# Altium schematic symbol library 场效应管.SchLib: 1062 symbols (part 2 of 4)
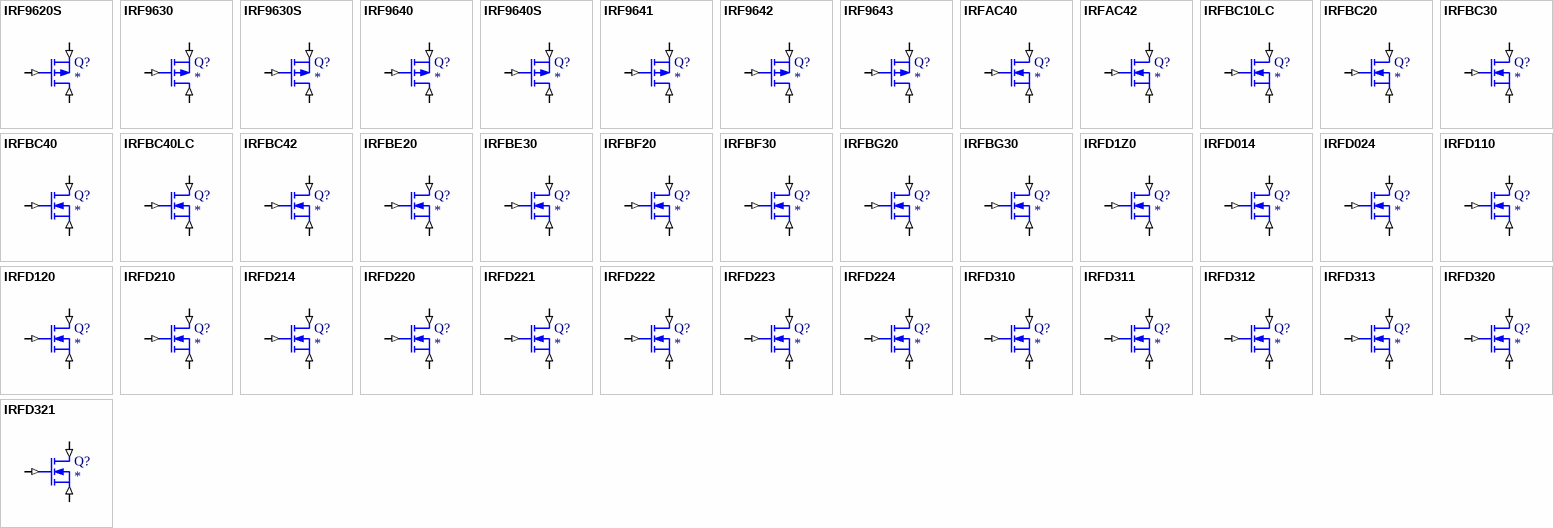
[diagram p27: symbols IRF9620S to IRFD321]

## IRFBC40
designator Q?
N-Channel MOSFET
simulation model IRFBC40 (SUBCKT)
pins: 1 D (in), 2 G (in), 3 S (in)
1 alternate drawing of the same symbol

## IRFBC40LC
designator Q?
N-Channel MOSFET
simulation model IRFBC40LC (SUBCKT)
pins: 1 D (in), 2 G (in), 3 S (in)
1 alternate drawing of the same symbol

## IRFBC42
designator Q?
N-Channel MOSFET
simulation model IRFBC42 (SUBCKT)
pins: 1 D (in), 2 G (in), 3 S (in)
1 alternate drawing of the same symbol

## IRFBE20
designator Q?
N-Channel MOSFET
simulation model IRFBE20 (SUBCKT)
pins: 1 D (in), 2 G (in), 3 S (in)
1 alternate drawing of the same symbol

## IRFBE30
designator Q?
N-Channel MOSFET
simulation model IRFBE30 (SUBCKT)
pins: 1 D (in), 2 G (in), 3 S (in)
1 alternate drawing of the same symbol

## IRFBF20
designator Q?
N-Channel MOSFET
simulation model IRFBF20 (SUBCKT)
pins: 1 D (in), 2 G (in), 3 S (in)
1 alternate drawing of the same symbol

## IRFBF30
designator Q?
N-Channel MOSFET
simulation model IRFBF30 (SUBCKT)
pins: 1 D (in), 2 G (in), 3 S (in)
1 alternate drawing of the same symbol

## IRFBG20
designator Q?
N-Channel MOSFET
simulation model IRFBG20 (SUBCKT)
pins: 1 D (in), 2 G (in), 3 S (in)
1 alternate drawing of the same symbol

## IRFBG30
designator Q?
N-Channel MOSFET
simulation model IRFBG30 (SUBCKT)
pins: 1 D (in), 2 G (in), 3 S (in)
1 alternate drawing of the same symbol

## IRFD1Z0
designator Q?
N-Channel MOSFET
simulation model IRFD1Z0 (SUBCKT)
pins: 1 D (in), 2 G (in), 3 S (in)
1 alternate drawing of the same symbol

## IRFD014
designator Q?
N-Channel MOSFET
simulation model IRFD014 (SUBCKT)
pins: 1 D (in), 2 G (in), 3 S (in)
1 alternate drawing of the same symbol

## IRFD024
designator Q?
N-Channel MOSFET
simulation model IRFD024 (SUBCKT)
pins: 1 D (in), 2 G (in), 3 S (in)
1 alternate drawing of the same symbol

## IRFD110
designator Q?
N-Channel MOSFET
simulation model IRFD110 (SUBCKT)
pins: 1 D (in), 2 G (in), 3 S (in)
1 alternate drawing of the same symbol

## IRFD120
designator Q?
N-Channel MOSFET
simulation model IRFD120 (SUBCKT)
pins: 1 D (in), 2 G (in), 3 S (in)
1 alternate drawing of the same symbol

## IRFD210
designator Q?
N-Channel MOSFET
simulation model IRFD210 (SUBCKT)
pins: 1 D (in), 2 G (in), 3 S (in)
1 alternate drawing of the same symbol

## IRFD214
designator Q?
N-Channel MOSFET
simulation model IRFD214 (SUBCKT)
pins: 1 D (in), 2 G (in), 3 S (in)
1 alternate drawing of the same symbol

## IRFD220
designator Q?
N-Channel MOSFET
simulation model IRFD220 (SUBCKT)
pins: 1 D (in), 2 G (in), 3 S (in)
1 alternate drawing of the same symbol

## IRFD221
designator Q?
N-Channel MOSFET
simulation model IRFD221 (SUBCKT)
pins: 1 D (in), 2 G (in), 3 S (in)
1 alternate drawing of the same symbol

## IRFD222
designator Q?
N-Channel MOSFET
simulation model IRFD222 (SUBCKT)
pins: 1 D (in), 2 G (in), 3 S (in)
1 alternate drawing of the same symbol

## IRFD223
designator Q?
N-Channel MOSFET
simulation model IRFD223 (SUBCKT)
pins: 1 D (in), 2 G (in), 3 S (in)
1 alternate drawing of the same symbol

## IRFD224
designator Q?
N-Channel MOSFET
simulation model IRFD224 (SUBCKT)
pins: 1 D (in), 2 G (in), 3 S (in)
1 alternate drawing of the same symbol

## IRFD310
designator Q?
N-Channel MOSFET
simulation model IRFD310 (SUBCKT)
pins: 1 D (in), 2 G (in), 3 S (in)
1 alternate drawing of the same symbol

## IRFD311
designator Q?
N-Channel MOSFET
simulation model IRFD311 (SUBCKT)
pins: 1 D (in), 2 G (in), 3 S (in)
1 alternate drawing of the same symbol

## IRFD312
designator Q?
N-Channel MOSFET
simulation model IRFD312 (SUBCKT)
pins: 1 D (in), 2 G (in), 3 S (in)
1 alternate drawing of the same symbol

## IRFD313
designator Q?
N-Channel MOSFET
simulation model IRFD313 (SUBCKT)
pins: 1 D (in), 2 G (in), 3 S (in)
1 alternate drawing of the same symbol

## IRFD320
designator Q?
N-Channel MOSFET
simulation model IRFD320 (SUBCKT)
pins: 1 D (in), 2 G (in), 3 S (in)
1 alternate drawing of the same symbol

## IRFD321
designator Q?
N-Channel MOSFET
simulation model IRFD321 (SUBCKT)
pins: 1 D (in), 2 G (in), 3 S (in)
1 alternate drawing of the same symbol

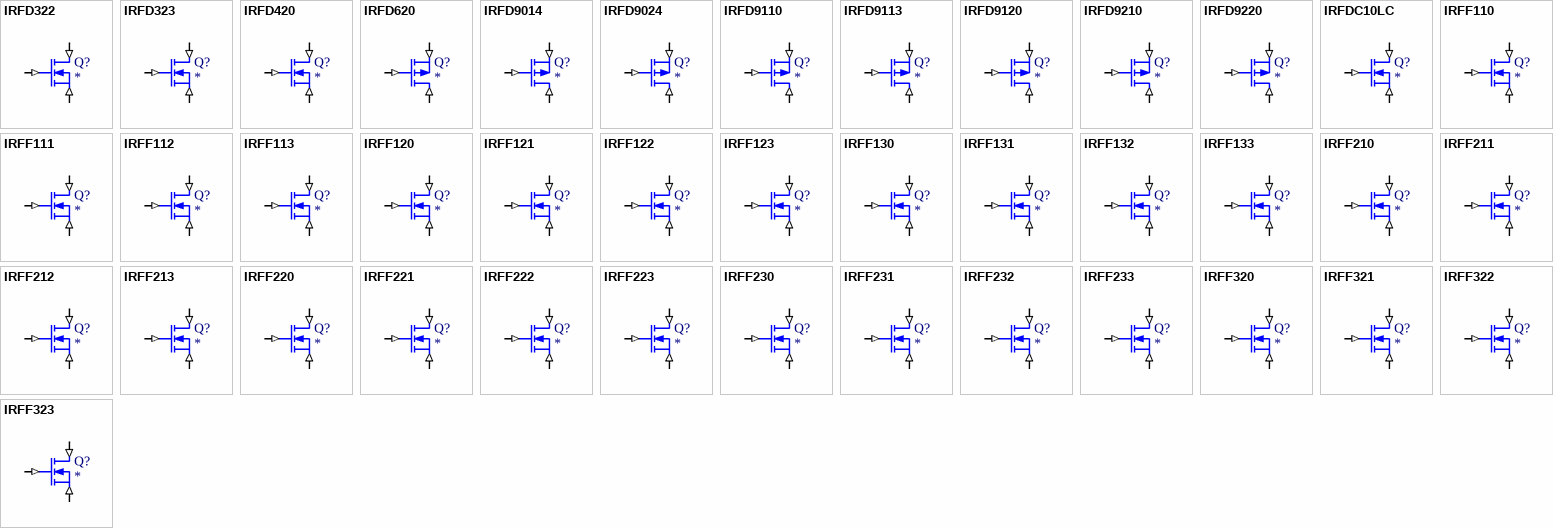
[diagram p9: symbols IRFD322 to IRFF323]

## IRFD322
designator Q?
N-Channel MOSFET
simulation model IRFD322 (SUBCKT)
pins: 1 D (in), 2 G (in), 3 S (in)
1 alternate drawing of the same symbol

## IRFD323
designator Q?
N-Channel MOSFET
simulation model IRFD323 (SUBCKT)
pins: 1 D (in), 2 G (in), 3 S (in)
1 alternate drawing of the same symbol

## IRFD420
designator Q?
N-Channel MOSFET
simulation model IRFD420 (SUBCKT)
pins: 1 D (in), 2 G (in), 3 S (in)
1 alternate drawing of the same symbol

## IRFD620
designator Q?
P-Channel MOSFET
simulation model IRFD620 (SUBCKT)
pins: 1 D (in), 2 G (in), 3 S (in)
1 alternate drawing of the same symbol

## IRFD9014
designator Q?
P-Channel MOSFET
simulation model IRFD9014 (SUBCKT)
pins: 1 D (in), 2 G (in), 3 S (in)
1 alternate drawing of the same symbol

## IRFD9024
designator Q?
P-Channel MOSFET
simulation model IRFD9024 (SUBCKT)
pins: 1 D (in), 2 G (in), 3 S (in)
1 alternate drawing of the same symbol

## IRFD9110
designator Q?
P-Channel MOSFET
simulation model IRFD9110 (SUBCKT)
pins: 1 D (in), 2 G (in), 3 S (in)
1 alternate drawing of the same symbol

## IRFD9113
designator Q?
P-Channel MOSFET
simulation model IRFD9113 (SUBCKT)
pins: 1 D (in), 2 G (in), 3 S (in)
1 alternate drawing of the same symbol

## IRFD9120
designator Q?
P-Channel MOSFET
simulation model IRFD9120 (SUBCKT)
pins: 1 D (in), 2 G (in), 3 S (in)
1 alternate drawing of the same symbol

## IRFD9210
designator Q?
P-Channel MOSFET
simulation model IRFD9210 (SUBCKT)
pins: 1 D (in), 2 G (in), 3 S (in)
1 alternate drawing of the same symbol

## IRFD9220
designator Q?
P-Channel MOSFET
simulation model IRFD9220 (SUBCKT)
pins: 1 D (in), 2 G (in), 3 S (in)
1 alternate drawing of the same symbol

## IRFDC10LC
designator Q?
N-Channel MOSFET
simulation model IRFDC10LC (SUBCKT)
pins: 1 D (in), 2 G (in), 3 S (in)
1 alternate drawing of the same symbol

## IRFF110
designator Q?
N-Channel MOSFET
simulation model IRFF110 (SUBCKT)
pins: 1 D (in), 2 G (in), 3 S (in)
1 alternate drawing of the same symbol

## IRFF111
designator Q?
N-Channel MOSFET
simulation model IRFF111 (SUBCKT)
pins: 1 D (in), 2 G (in), 3 S (in)
1 alternate drawing of the same symbol

## IRFF112
designator Q?
N-Channel MOSFET
simulation model IRFF112 (SUBCKT)
pins: 1 D (in), 2 G (in), 3 S (in)
1 alternate drawing of the same symbol

## IRFF113
designator Q?
N-Channel MOSFET
simulation model IRFF113 (SUBCKT)
pins: 1 D (in), 2 G (in), 3 S (in)
1 alternate drawing of the same symbol

## IRFF120
designator Q?
N-Channel MOSFET
simulation model IRFF120 (SUBCKT)
pins: 1 D (in), 2 G (in), 3 S (in)
1 alternate drawing of the same symbol

## IRFF121
designator Q?
N-Channel MOSFET
simulation model IRFF121 (SUBCKT)
pins: 1 D (in), 2 G (in), 3 S (in)
1 alternate drawing of the same symbol

## IRFF122
designator Q?
N-Channel MOSFET
simulation model IRFF122 (SUBCKT)
pins: 1 D (in), 2 G (in), 3 S (in)
1 alternate drawing of the same symbol

## IRFF123
designator Q?
N-Channel MOSFET
simulation model IRFF123 (SUBCKT)
pins: 1 D (in), 2 G (in), 3 S (in)
1 alternate drawing of the same symbol

## IRFF130
designator Q?
N-Channel MOSFET
simulation model IRFF130 (SUBCKT)
pins: 1 D (in), 2 G (in), 3 S (in)
1 alternate drawing of the same symbol

## IRFF131
designator Q?
N-Channel MOSFET
simulation model IRFF131 (SUBCKT)
pins: 1 D (in), 2 G (in), 3 S (in)
1 alternate drawing of the same symbol

## IRFF132
designator Q?
N-Channel MOSFET
simulation model IRFF132 (SUBCKT)
pins: 1 D (in), 2 G (in), 3 S (in)
1 alternate drawing of the same symbol

## IRFF133
designator Q?
N-Channel MOSFET
simulation model IRFF133 (SUBCKT)
pins: 1 D (in), 2 G (in), 3 S (in)
1 alternate drawing of the same symbol

## IRFF210
designator Q?
N-Channel MOSFET
simulation model IRFF210 (SUBCKT)
pins: 1 D (in), 2 G (in), 3 S (in)
1 alternate drawing of the same symbol

## IRFF211
designator Q?
N-Channel MOSFET
simulation model IRFF211 (SUBCKT)
pins: 1 D (in), 2 G (in), 3 S (in)
1 alternate drawing of the same symbol

## IRFF212
designator Q?
N-Channel MOSFET
simulation model IRFF212 (SUBCKT)
pins: 1 D (in), 2 G (in), 3 S (in)
1 alternate drawing of the same symbol

## IRFF213
designator Q?
N-Channel MOSFET
simulation model IRFF213 (SUBCKT)
pins: 1 D (in), 2 G (in), 3 S (in)
1 alternate drawing of the same symbol

## IRFF220
designator Q?
N-Channel MOSFET
simulation model IRFF220 (SUBCKT)
pins: 1 D (in), 2 G (in), 3 S (in)
1 alternate drawing of the same symbol

## IRFF221
designator Q?
N-Channel MOSFET
simulation model IRFF221 (SUBCKT)
pins: 1 D (in), 2 G (in), 3 S (in)
1 alternate drawing of the same symbol

## IRFF222
designator Q?
N-Channel MOSFET
simulation model IRFF222 (SUBCKT)
pins: 1 D (in), 2 G (in), 3 S (in)
1 alternate drawing of the same symbol

## IRFF223
designator Q?
N-Channel MOSFET
simulation model IRFF223 (SUBCKT)
pins: 1 D (in), 2 G (in), 3 S (in)
1 alternate drawing of the same symbol

## IRFF230
designator Q?
N-Channel MOSFET
simulation model IRFF230 (SUBCKT)
pins: 1 D (in), 2 G (in), 3 S (in)
1 alternate drawing of the same symbol

## IRFF231
designator Q?
N-Channel MOSFET
simulation model IRFF231 (SUBCKT)
pins: 1 D (in), 2 G (in), 3 S (in)
1 alternate drawing of the same symbol

## IRFF232
designator Q?
N-Channel MOSFET
simulation model IRFF232 (SUBCKT)
pins: 1 D (in), 2 G (in), 3 S (in)
1 alternate drawing of the same symbol

## IRFF233
designator Q?
N-Channel MOSFET
simulation model IRFF233 (SUBCKT)
pins: 1 D (in), 2 G (in), 3 S (in)
1 alternate drawing of the same symbol

## IRFF320
designator Q?
N-Channel MOSFET
simulation model IRFF320 (SUBCKT)
pins: 1 D (in), 2 G (in), 3 S (in)
1 alternate drawing of the same symbol

## IRFF321
designator Q?
N-Channel MOSFET
simulation model IRFF321 (SUBCKT)
pins: 1 D (in), 2 G (in), 3 S (in)
1 alternate drawing of the same symbol

## IRFF322
designator Q?
N-Channel MOSFET
simulation model IRFF322 (SUBCKT)
pins: 1 D (in), 2 G (in), 3 S (in)
1 alternate drawing of the same symbol

## IRFF323
designator Q?
N-Channel MOSFET
simulation model IRFF323 (SUBCKT)
pins: 1 D (in), 2 G (in), 3 S (in)
1 alternate drawing of the same symbol

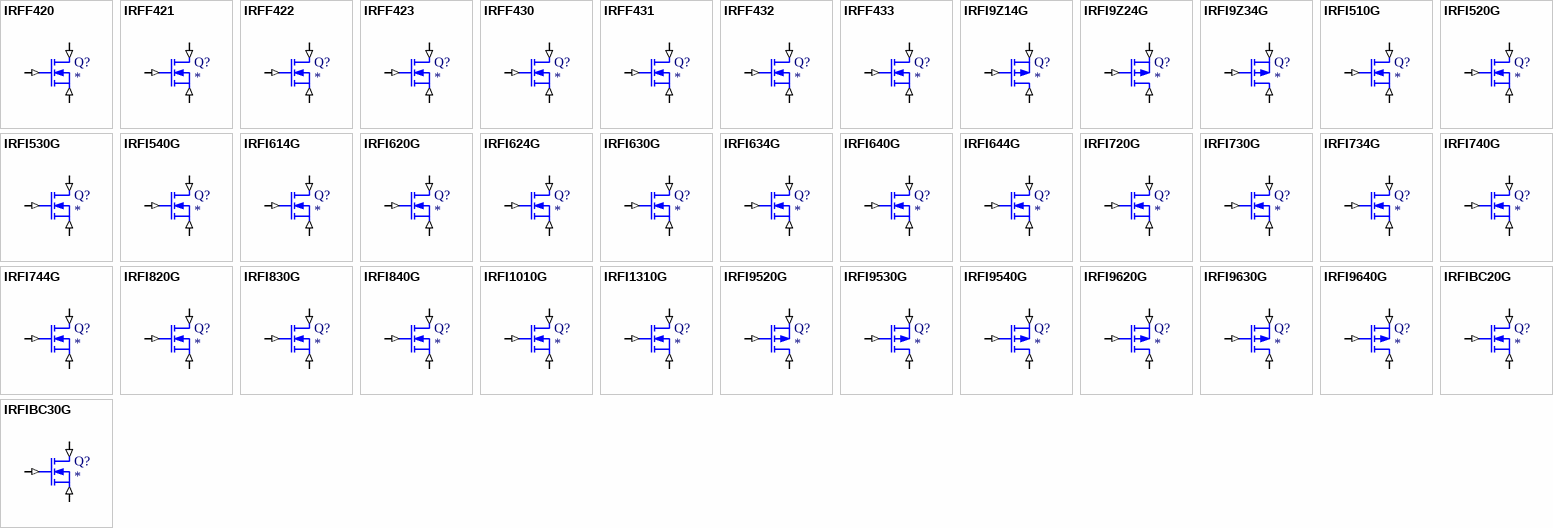
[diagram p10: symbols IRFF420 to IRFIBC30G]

## IRFF420
designator Q?
N-Channel MOSFET
simulation model IRFF420 (SUBCKT)
pins: 1 D (in), 2 G (in), 3 S (in)
1 alternate drawing of the same symbol

## IRFF421
designator Q?
N-Channel MOSFET
simulation model IRFF421 (SUBCKT)
pins: 1 D (in), 2 G (in), 3 S (in)
1 alternate drawing of the same symbol

## IRFF422
designator Q?
N-Channel MOSFET
simulation model IRFF422 (SUBCKT)
pins: 1 D (in), 2 G (in), 3 S (in)
1 alternate drawing of the same symbol

## IRFF423
designator Q?
N-Channel MOSFET
simulation model IRFF423 (SUBCKT)
pins: 1 D (in), 2 G (in), 3 S (in)
1 alternate drawing of the same symbol

## IRFF430
designator Q?
N-Channel MOSFET
simulation model IRFF430 (SUBCKT)
pins: 1 D (in), 2 G (in), 3 S (in)
1 alternate drawing of the same symbol

## IRFF431
designator Q?
N-Channel MOSFET
simulation model IRFF431 (SUBCKT)
pins: 1 D (in), 2 G (in), 3 S (in)
1 alternate drawing of the same symbol

## IRFF432
designator Q?
N-Channel MOSFET
simulation model IRFF432 (SUBCKT)
pins: 1 D (in), 2 G (in), 3 S (in)
1 alternate drawing of the same symbol

## IRFF433
designator Q?
N-Channel MOSFET
simulation model IRFF433 (SUBCKT)
pins: 1 D (in), 2 G (in), 3 S (in)
1 alternate drawing of the same symbol

## IRFI9Z14G
designator Q?
P-Channel MOSFET
simulation model IRFI9Z14G (SUBCKT)
pins: 1 D (in), 2 G (in), 3 S (in)
1 alternate drawing of the same symbol

## IRFI9Z24G
designator Q?
P-Channel MOSFET
simulation model IRFI9Z24G (SUBCKT)
pins: 1 D (in), 2 G (in), 3 S (in)
1 alternate drawing of the same symbol

## IRFI9Z34G
designator Q?
P-Channel MOSFET
simulation model IRFI9Z34G (SUBCKT)
pins: 1 D (in), 2 G (in), 3 S (in)
1 alternate drawing of the same symbol

## IRFI510G
designator Q?
N-Channel MOSFET
simulation model IRFI510G (SUBCKT)
pins: 1 D (in), 2 G (in), 3 S (in)
1 alternate drawing of the same symbol

## IRFI520G
designator Q?
N-Channel MOSFET
simulation model IRFI520G (SUBCKT)
pins: 1 D (in), 2 G (in), 3 S (in)
1 alternate drawing of the same symbol

## IRFI530G
designator Q?
N-Channel MOSFET
simulation model IRFI530G (SUBCKT)
pins: 1 D (in), 2 G (in), 3 S (in)
1 alternate drawing of the same symbol

## IRFI540G
designator Q?
N-Channel MOSFET
simulation model IRFI540G (SUBCKT)
pins: 1 D (in), 2 G (in), 3 S (in)
1 alternate drawing of the same symbol

## IRFI614G
designator Q?
N-Channel MOSFET
simulation model IRFI614G (SUBCKT)
pins: 1 D (in), 2 G (in), 3 S (in)
1 alternate drawing of the same symbol

## IRFI620G
designator Q?
N-Channel MOSFET
simulation model IRFI620G (SUBCKT)
pins: 1 D (in), 2 G (in), 3 S (in)
1 alternate drawing of the same symbol

## IRFI624G
designator Q?
N-Channel MOSFET
simulation model IRFI624G (SUBCKT)
pins: 1 D (in), 2 G (in), 3 S (in)
1 alternate drawing of the same symbol

## IRFI630G
designator Q?
N-Channel MOSFET
simulation model IRFI630G (SUBCKT)
pins: 1 D (in), 2 G (in), 3 S (in)
1 alternate drawing of the same symbol

## IRFI634G
designator Q?
N-Channel MOSFET
simulation model IRFI634G (SUBCKT)
pins: 1 D (in), 2 G (in), 3 S (in)
1 alternate drawing of the same symbol

## IRFI640G
designator Q?
N-Channel MOSFET
simulation model IRFI640G (SUBCKT)
pins: 1 D (in), 2 G (in), 3 S (in)
1 alternate drawing of the same symbol

## IRFI644G
designator Q?
N-Channel MOSFET
simulation model IRFI644G (SUBCKT)
pins: 1 D (in), 2 G (in), 3 S (in)
1 alternate drawing of the same symbol

## IRFI720G
designator Q?
N-Channel MOSFET
simulation model IRFI720G (SUBCKT)
pins: 1 D (in), 2 G (in), 3 S (in)
1 alternate drawing of the same symbol

## IRFI730G
designator Q?
N-Channel MOSFET
simulation model IRFI730G (SUBCKT)
pins: 1 D (in), 2 G (in), 3 S (in)
1 alternate drawing of the same symbol

## IRFI734G
designator Q?
N-Channel MOSFET
simulation model IRFI734G (SUBCKT)
pins: 1 D (in), 2 G (in), 3 S (in)
1 alternate drawing of the same symbol

## IRFI740G
designator Q?
N-Channel MOSFET
simulation model IRFI740G (SUBCKT)
pins: 1 D (in), 2 G (in), 3 S (in)
1 alternate drawing of the same symbol

## IRFI744G
designator Q?
N-Channel MOSFET
simulation model IRFI744G (SUBCKT)
pins: 1 D (in), 2 G (in), 3 S (in)
1 alternate drawing of the same symbol

## IRFI820G
designator Q?
N-Channel MOSFET
simulation model IRFI820G (SUBCKT)
pins: 1 D (in), 2 G (in), 3 S (in)
1 alternate drawing of the same symbol

## IRFI830G
designator Q?
N-Channel MOSFET
simulation model IRFI830G (SUBCKT)
pins: 1 D (in), 2 G (in), 3 S (in)
1 alternate drawing of the same symbol

## IRFI840G
designator Q?
N-Channel MOSFET
simulation model IRFI840G (SUBCKT)
pins: 1 D (in), 2 G (in), 3 S (in)
1 alternate drawing of the same symbol

## IRFI1010G
designator Q?
N-Channel MOSFET
simulation model IRFI1010G (SUBCKT)
pins: 1 D (in), 2 G (in), 3 S (in)
1 alternate drawing of the same symbol

## IRFI1310G
designator Q?
N-Channel MOSFET
simulation model IRFI1310G (SUBCKT)
pins: 1 D (in), 2 G (in), 3 S (in)
1 alternate drawing of the same symbol

## IRFI9520G
designator Q?
P-Channel MOSFET
simulation model IRFI9520G (SUBCKT)
pins: 1 D (in), 2 G (in), 3 S (in)
1 alternate drawing of the same symbol

## IRFI9530G
designator Q?
P-Channel MOSFET
simulation model IRFI9530G (SUBCKT)
pins: 1 D (in), 2 G (in), 3 S (in)
1 alternate drawing of the same symbol

## IRFI9540G
designator Q?
P-Channel MOSFET
simulation model IRFI9540G (SUBCKT)
pins: 1 D (in), 2 G (in), 3 S (in)
1 alternate drawing of the same symbol

## IRFI9620G
designator Q?
P-Channel MOSFET
simulation model IRFI9620G (SUBCKT)
pins: 1 D (in), 2 G (in), 3 S (in)
1 alternate drawing of the same symbol

## IRFI9630G
designator Q?
P-Channel MOSFET
simulation model IRFI9630G (SUBCKT)
pins: 1 D (in), 2 G (in), 3 S (in)
1 alternate drawing of the same symbol

## IRFI9640G
designator Q?
P-Channel MOSFET
simulation model IRFI9640G (SUBCKT)
pins: 1 D (in), 2 G (in), 3 S (in)
1 alternate drawing of the same symbol

## IRFIBC20G
designator Q?
N-Channel MOSFET
simulation model IRFIBC20G (SUBCKT)
pins: 1 D (in), 2 G (in), 3 S (in)
1 alternate drawing of the same symbol

## IRFIBC30G
designator Q?
N-Channel MOSFET
simulation model IRFIBC30G (SUBCKT)
pins: 1 D (in), 2 G (in), 3 S (in)
1 alternate drawing of the same symbol

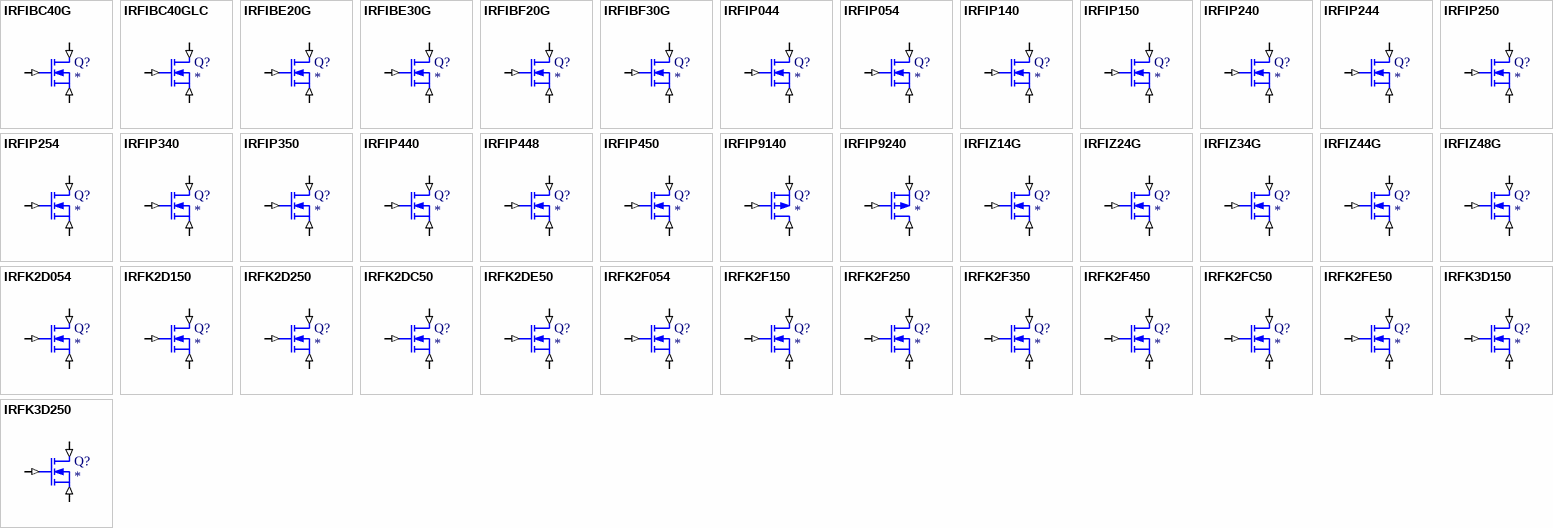
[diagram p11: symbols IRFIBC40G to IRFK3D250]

## IRFIBC40G
designator Q?
N-Channel MOSFET
simulation model IRFIBC40G (SUBCKT)
pins: 1 D (in), 2 G (in), 3 S (in)
1 alternate drawing of the same symbol

## IRFIBC40GLC
designator Q?
N-Channel MOSFET
simulation model IRFIBC40GLC (SUBCKT)
pins: 1 D (in), 2 G (in), 3 S (in)
1 alternate drawing of the same symbol

## IRFIBE20G
designator Q?
N-Channel MOSFET
simulation model IRFIBE20G (SUBCKT)
pins: 1 D (in), 2 G (in), 3 S (in)
1 alternate drawing of the same symbol

## IRFIBE30G
designator Q?
N-Channel MOSFET
simulation model IRFIBE30G (SUBCKT)
pins: 1 D (in), 2 G (in), 3 S (in)
1 alternate drawing of the same symbol

## IRFIBF20G
designator Q?
N-Channel MOSFET
simulation model IRFIBF20G (SUBCKT)
pins: 1 D (in), 2 G (in), 3 S (in)
1 alternate drawing of the same symbol

## IRFIBF30G
designator Q?
N-Channel MOSFET
simulation model IRFIBF30G (SUBCKT)
pins: 1 D (in), 2 G (in), 3 S (in)
1 alternate drawing of the same symbol

## IRFIP044
designator Q?
N-Channel MOSFET
simulation model IRFIP044 (SUBCKT)
pins: 1 D (in), 2 G (in), 3 S (in)
1 alternate drawing of the same symbol

## IRFIP054
designator Q?
N-Channel MOSFET
simulation model IRFIP054 (SUBCKT)
pins: 1 D (in), 2 G (in), 3 S (in)
1 alternate drawing of the same symbol

## IRFIP140
designator Q?
N-Channel MOSFET
simulation model IRFIP140 (SUBCKT)
pins: 1 D (in), 2 G (in), 3 S (in)
1 alternate drawing of the same symbol

## IRFIP150
designator Q?
N-Channel MOSFET
simulation model IRFIP150 (SUBCKT)
pins: 1 D (in), 2 G (in), 3 S (in)
1 alternate drawing of the same symbol

## IRFIP240
designator Q?
N-Channel MOSFET
simulation model IRFIP240 (SUBCKT)
pins: 1 D (in), 2 G (in), 3 S (in)
1 alternate drawing of the same symbol

## IRFIP244
designator Q?
N-Channel MOSFET
simulation model IRFIP244 (SUBCKT)
pins: 1 D (in), 2 G (in), 3 S (in)
1 alternate drawing of the same symbol

## IRFIP250
designator Q?
N-Channel MOSFET
simulation model IRFIP250 (SUBCKT)
pins: 1 D (in), 2 G (in), 3 S (in)
1 alternate drawing of the same symbol

## IRFIP254
designator Q?
N-Channel MOSFET
simulation model IRFIP254 (SUBCKT)
pins: 1 D (in), 2 G (in), 3 S (in)
1 alternate drawing of the same symbol

## IRFIP340
designator Q?
N-Channel MOSFET
simulation model IRFIP340 (SUBCKT)
pins: 1 D (in), 2 G (in), 3 S (in)
1 alternate drawing of the same symbol

## IRFIP350
designator Q?
N-Channel MOSFET
simulation model IRFIP350 (SUBCKT)
pins: 1 D (in), 2 G (in), 3 S (in)
1 alternate drawing of the same symbol

## IRFIP440
designator Q?
N-Channel MOSFET
simulation model IRFIP440 (SUBCKT)
pins: 1 D (in), 2 G (in), 3 S (in)
1 alternate drawing of the same symbol

## IRFIP448
designator Q?
N-Channel MOSFET
simulation model IRFIP448 (SUBCKT)
pins: 1 D (in), 2 G (in), 3 S (in)
1 alternate drawing of the same symbol

## IRFIP450
designator Q?
N-Channel MOSFET
simulation model IRFIP450 (SUBCKT)
pins: 1 D (in), 2 G (in), 3 S (in)
1 alternate drawing of the same symbol

## IRFIP9140
designator Q?
P-Channel MOSFET
simulation model IRFIP9140 (SUBCKT)
pins: 1 D (in), 2 G (in), 3 S (in)
1 alternate drawing of the same symbol

## IRFIP9240
designator Q?
P-Channel MOSFET
simulation model IRFIP9240 (SUBCKT)
pins: 1 D (in), 2 G (in), 3 S (in)
1 alternate drawing of the same symbol

## IRFIZ14G
designator Q?
N-Channel MOSFET
simulation model IRFIZ14G (SUBCKT)
pins: 1 D (in), 2 G (in), 3 S (in)
1 alternate drawing of the same symbol

## IRFIZ24G
designator Q?
N-Channel MOSFET
simulation model IRFIZ24G (SUBCKT)
pins: 1 D (in), 2 G (in), 3 S (in)
1 alternate drawing of the same symbol

## IRFIZ34G
designator Q?
N-Channel MOSFET
simulation model IRFIZ34G (SUBCKT)
pins: 1 D (in), 2 G (in), 3 S (in)
1 alternate drawing of the same symbol

## IRFIZ44G
designator Q?
N-Channel MOSFET
simulation model IRFIZ44G (SUBCKT)
pins: 1 D (in), 2 G (in), 3 S (in)
1 alternate drawing of the same symbol

## IRFIZ48G
designator Q?
N-Channel MOSFET
simulation model IRFIZ48G (SUBCKT)
pins: 1 D (in), 2 G (in), 3 S (in)
1 alternate drawing of the same symbol

## IRFK2D054
designator Q?
N-Channel MOSFET
simulation model IRFK2D054 (SUBCKT)
pins: 1 D (in), 2 G (in), 3 S (in)
1 alternate drawing of the same symbol

## IRFK2D150
designator Q?
N-Channel MOSFET
simulation model IRFK2D150 (SUBCKT)
pins: 1 D (in), 2 G (in), 3 S (in)
1 alternate drawing of the same symbol

## IRFK2D250
designator Q?
N-Channel MOSFET
simulation model IRFK2D250 (SUBCKT)
pins: 1 D (in), 2 G (in), 3 S (in)
1 alternate drawing of the same symbol

## IRFK2DC50
designator Q?
N-Channel MOSFET
simulation model IRFK2DC50 (SUBCKT)
pins: 1 D (in), 2 G (in), 3 S (in)
1 alternate drawing of the same symbol

## IRFK2DE50
designator Q?
N-Channel MOSFET
simulation model IRFK2DE50 (SUBCKT)
pins: 1 D (in), 2 G (in), 3 S (in)
1 alternate drawing of the same symbol

## IRFK2F054
designator Q?
N-Channel MOSFET
simulation model IRFK2F054 (SUBCKT)
pins: 1 D (in), 2 G (in), 3 S (in)
1 alternate drawing of the same symbol

## IRFK2F150
designator Q?
N-Channel MOSFET
simulation model IRFK2F150 (SUBCKT)
pins: 1 D (in), 2 G (in), 3 S (in)
1 alternate drawing of the same symbol

## IRFK2F250
designator Q?
N-Channel MOSFET
simulation model IRFK2F250 (SUBCKT)
pins: 1 D (in), 2 G (in), 3 S (in)
1 alternate drawing of the same symbol

## IRFK2F350
designator Q?
N-Channel MOSFET
simulation model IRFK2F350 (SUBCKT)
pins: 1 D (in), 2 G (in), 3 S (in)
1 alternate drawing of the same symbol

## IRFK2F450
designator Q?
N-Channel MOSFET
simulation model IRFK2F450 (SUBCKT)
pins: 1 D (in), 2 G (in), 3 S (in)
1 alternate drawing of the same symbol

## IRFK2FC50
designator Q?
N-Channel MOSFET
simulation model IRFK2FC50 (SUBCKT)
pins: 1 D (in), 2 G (in), 3 S (in)
1 alternate drawing of the same symbol

## IRFK2FE50
designator Q?
N-Channel MOSFET
simulation model IRFK2FE50 (SUBCKT)
pins: 1 D (in), 2 G (in), 3 S (in)
1 alternate drawing of the same symbol

## IRFK3D150
designator Q?
N-Channel MOSFET
simulation model IRFK3D150 (SUBCKT)
pins: 1 D (in), 2 G (in), 3 S (in)
1 alternate drawing of the same symbol

## IRFK3D250
designator Q?
N-Channel MOSFET
simulation model IRFK3D250 (SUBCKT)
pins: 1 D (in), 2 G (in), 3 S (in)
1 alternate drawing of the same symbol

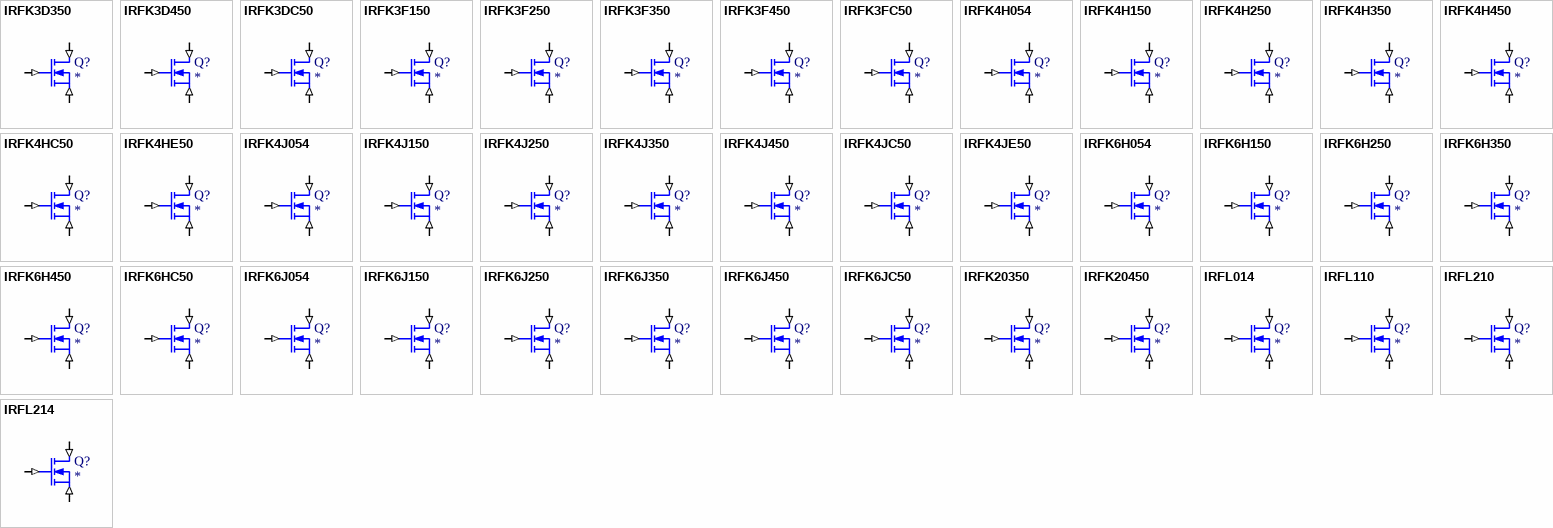
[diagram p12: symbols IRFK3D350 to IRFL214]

## IRFK3D350
designator Q?
N-Channel MOSFET
simulation model IRFK3D350 (SUBCKT)
pins: 1 D (in), 2 G (in), 3 S (in)
1 alternate drawing of the same symbol

## IRFK3D450
designator Q?
N-Channel MOSFET
simulation model IRFK3D450 (SUBCKT)
pins: 1 D (in), 2 G (in), 3 S (in)
1 alternate drawing of the same symbol

## IRFK3DC50
designator Q?
N-Channel MOSFET
simulation model IRFK3DC50 (SUBCKT)
pins: 1 D (in), 2 G (in), 3 S (in)
1 alternate drawing of the same symbol

## IRFK3F150
designator Q?
N-Channel MOSFET
simulation model IRFK3F150 (SUBCKT)
pins: 1 D (in), 2 G (in), 3 S (in)
1 alternate drawing of the same symbol

## IRFK3F250
designator Q?
N-Channel MOSFET
simulation model IRFK3F250 (SUBCKT)
pins: 1 D (in), 2 G (in), 3 S (in)
1 alternate drawing of the same symbol

## IRFK3F350
designator Q?
N-Channel MOSFET
simulation model IRFK3F350 (SUBCKT)
pins: 1 D (in), 2 G (in), 3 S (in)
1 alternate drawing of the same symbol

## IRFK3F450
designator Q?
N-Channel MOSFET
simulation model IRFK3F450 (SUBCKT)
pins: 1 D (in), 2 G (in), 3 S (in)
1 alternate drawing of the same symbol

## IRFK3FC50
designator Q?
N-Channel MOSFET
simulation model IRFK3FC50 (SUBCKT)
pins: 1 D (in), 2 G (in), 3 S (in)
1 alternate drawing of the same symbol

## IRFK4H054
designator Q?
N-Channel MOSFET
simulation model IRFK4H054 (SUBCKT)
pins: 1 D (in), 2 G (in), 3 S (in)
1 alternate drawing of the same symbol

## IRFK4H150
designator Q?
N-Channel MOSFET
simulation model IRFK4H150 (SUBCKT)
pins: 1 D (in), 2 G (in), 3 S (in)
1 alternate drawing of the same symbol

## IRFK4H250
designator Q?
N-Channel MOSFET
simulation model IRFK4H250 (SUBCKT)
pins: 1 D (in), 2 G (in), 3 S (in)
1 alternate drawing of the same symbol

## IRFK4H350
designator Q?
N-Channel MOSFET
simulation model IRFK4H350 (SUBCKT)
pins: 1 D (in), 2 G (in), 3 S (in)
1 alternate drawing of the same symbol

## IRFK4H450
designator Q?
N-Channel MOSFET
simulation model IRFK4H450 (SUBCKT)
pins: 1 D (in), 2 G (in), 3 S (in)
1 alternate drawing of the same symbol

## IRFK4HC50
designator Q?
N-Channel MOSFET
simulation model IRFK4HC50 (SUBCKT)
pins: 1 D (in), 2 G (in), 3 S (in)
1 alternate drawing of the same symbol

## IRFK4HE50
designator Q?
N-Channel MOSFET
simulation model IRFK4HE50 (SUBCKT)
pins: 1 D (in), 2 G (in), 3 S (in)
1 alternate drawing of the same symbol

## IRFK4J054
designator Q?
N-Channel MOSFET
simulation model IRFK4J054 (SUBCKT)
pins: 1 D (in), 2 G (in), 3 S (in)
1 alternate drawing of the same symbol

## IRFK4J150
designator Q?
N-Channel MOSFET
simulation model IRFK4J150 (SUBCKT)
pins: 1 D (in), 2 G (in), 3 S (in)
1 alternate drawing of the same symbol

## IRFK4J250
designator Q?
N-Channel MOSFET
simulation model IRFK4J250 (SUBCKT)
pins: 1 D (in), 2 G (in), 3 S (in)
1 alternate drawing of the same symbol

## IRFK4J350
designator Q?
N-Channel MOSFET
simulation model IRFK4J350 (SUBCKT)
pins: 1 D (in), 2 G (in), 3 S (in)
1 alternate drawing of the same symbol

## IRFK4J450
designator Q?
N-Channel MOSFET
simulation model IRFK4J450 (SUBCKT)
pins: 1 D (in), 2 G (in), 3 S (in)
1 alternate drawing of the same symbol

## IRFK4JC50
designator Q?
N-Channel MOSFET
simulation model IRFK4JC50 (SUBCKT)
pins: 1 D (in), 2 G (in), 3 S (in)
1 alternate drawing of the same symbol

## IRFK4JE50
designator Q?
N-Channel MOSFET
simulation model IRFK4JE50 (SUBCKT)
pins: 1 D (in), 2 G (in), 3 S (in)
1 alternate drawing of the same symbol

## IRFK6H054
designator Q?
N-Channel MOSFET
simulation model IRFK6H054 (SUBCKT)
pins: 1 D (in), 2 G (in), 3 S (in)
1 alternate drawing of the same symbol

## IRFK6H150
designator Q?
N-Channel MOSFET
simulation model IRFK6H150 (SUBCKT)
pins: 1 D (in), 2 G (in), 3 S (in)
1 alternate drawing of the same symbol

## IRFK6H250
designator Q?
N-Channel MOSFET
simulation model IRFK6H250 (SUBCKT)
pins: 1 D (in), 2 G (in), 3 S (in)
1 alternate drawing of the same symbol

## IRFK6H350
designator Q?
N-Channel MOSFET
simulation model IRFK6H350 (SUBCKT)
pins: 1 D (in), 2 G (in), 3 S (in)
1 alternate drawing of the same symbol

## IRFK6H450
designator Q?
N-Channel MOSFET
simulation model IRFK6H450 (SUBCKT)
pins: 1 D (in), 2 G (in), 3 S (in)
1 alternate drawing of the same symbol

## IRFK6HC50
designator Q?
N-Channel MOSFET
simulation model IRFK6HC50 (SUBCKT)
pins: 1 D (in), 2 G (in), 3 S (in)
1 alternate drawing of the same symbol

## IRFK6J054
designator Q?
N-Channel MOSFET
simulation model IRFK6J054 (SUBCKT)
pins: 1 D (in), 2 G (in), 3 S (in)
1 alternate drawing of the same symbol

## IRFK6J150
designator Q?
N-Channel MOSFET
simulation model IRFK6J150 (SUBCKT)
pins: 1 D (in), 2 G (in), 3 S (in)
1 alternate drawing of the same symbol

## IRFK6J250
designator Q?
N-Channel MOSFET
simulation model IRFK6J250 (SUBCKT)
pins: 1 D (in), 2 G (in), 3 S (in)
1 alternate drawing of the same symbol

## IRFK6J350
designator Q?
N-Channel MOSFET
simulation model IRFK6J350 (SUBCKT)
pins: 1 D (in), 2 G (in), 3 S (in)
1 alternate drawing of the same symbol

## IRFK6J450
designator Q?
N-Channel MOSFET
simulation model IRFK6J450 (SUBCKT)
pins: 1 D (in), 2 G (in), 3 S (in)
1 alternate drawing of the same symbol

## IRFK6JC50
designator Q?
N-Channel MOSFET
simulation model IRFK6JC50 (SUBCKT)
pins: 1 D (in), 2 G (in), 3 S (in)
1 alternate drawing of the same symbol

## IRFK20350
designator Q?
N-Channel MOSFET
simulation model IRFK20350 (SUBCKT)
pins: 1 D (in), 2 G (in), 3 S (in)
1 alternate drawing of the same symbol

## IRFK20450
designator Q?
N-Channel MOSFET
simulation model IRFK20450 (SUBCKT)
pins: 1 D (in), 2 G (in), 3 S (in)
1 alternate drawing of the same symbol

## IRFL014
designator Q?
N-Channel MOSFET
simulation model IRFL014 (SUBCKT)
pins: 1 D (in), 2 G (in), 3 S (in)
1 alternate drawing of the same symbol

## IRFL110
designator Q?
N-Channel MOSFET
simulation model IRFL110 (SUBCKT)
pins: 1 D (in), 2 G (in), 3 S (in)
1 alternate drawing of the same symbol

## IRFL210
designator Q?
N-Channel MOSFET
simulation model IRFL210 (SUBCKT)
pins: 1 D (in), 2 G (in), 3 S (in)
1 alternate drawing of the same symbol

## IRFL214
designator Q?
N-Channel MOSFET
simulation model IRFL214 (SUBCKT)
pins: 1 D (in), 2 G (in), 3 S (in)
1 alternate drawing of the same symbol

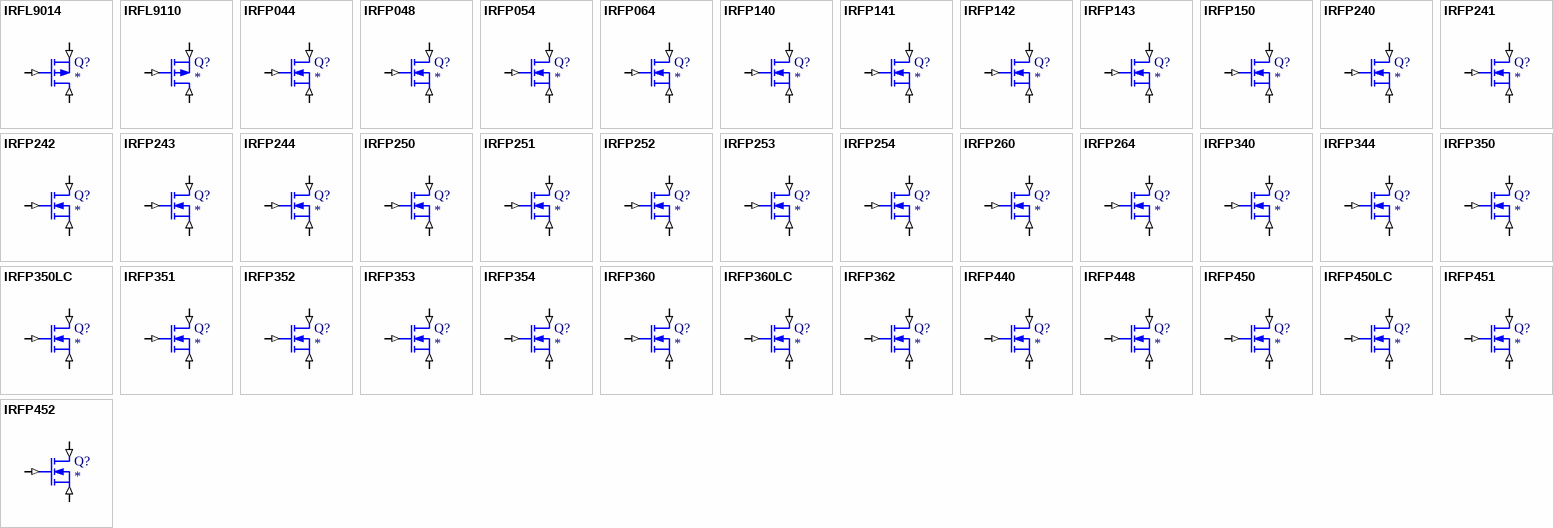
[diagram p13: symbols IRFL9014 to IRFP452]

## IRFL9014
designator Q?
P-Channel MOSFET
simulation model IRFL9014 (SUBCKT)
pins: 1 D (in), 2 G (in), 3 S (in)
1 alternate drawing of the same symbol

## IRFL9110
designator Q?
P-Channel MOSFET
simulation model IRFL9110 (SUBCKT)
pins: 1 D (in), 2 G (in), 3 S (in)
1 alternate drawing of the same symbol

## IRFP044
designator Q?
N-Channel MOSFET
simulation model IRFP044 (SUBCKT)
pins: 1 D (in), 2 G (in), 3 S (in)
1 alternate drawing of the same symbol

## IRFP048
designator Q?
N-Channel MOSFET
simulation model IRFP048 (SUBCKT)
pins: 1 D (in), 2 G (in), 3 S (in)
1 alternate drawing of the same symbol

## IRFP054
designator Q?
N-Channel MOSFET
simulation model IRFP054 (SUBCKT)
pins: 1 D (in), 2 G (in), 3 S (in)
1 alternate drawing of the same symbol

## IRFP064
designator Q?
N-Channel MOSFET
simulation model IRFP064 (SUBCKT)
pins: 1 D (in), 2 G (in), 3 S (in)
1 alternate drawing of the same symbol

## IRFP140
designator Q?
N-Channel MOSFET
simulation model IRFP140 (SUBCKT)
pins: 1 D (in), 2 G (in), 3 S (in)
1 alternate drawing of the same symbol

## IRFP141
designator Q?
N-Channel MOSFET
simulation model IRFP141 (SUBCKT)
pins: 1 D (in), 2 G (in), 3 S (in)
1 alternate drawing of the same symbol

## IRFP142
designator Q?
N-Channel MOSFET
simulation model IRFP142 (SUBCKT)
pins: 1 D (in), 2 G (in), 3 S (in)
1 alternate drawing of the same symbol

## IRFP143
designator Q?
N-Channel MOSFET
simulation model IRFP143 (SUBCKT)
pins: 1 D (in), 2 G (in), 3 S (in)
1 alternate drawing of the same symbol

## IRFP150
designator Q?
N-Channel MOSFET
simulation model IRFP150 (SUBCKT)
pins: 1 D (in), 2 G (in), 3 S (in)
1 alternate drawing of the same symbol

## IRFP240
designator Q?
N-Channel MOSFET
simulation model IRFP240 (SUBCKT)
pins: 1 D (in), 2 G (in), 3 S (in)
1 alternate drawing of the same symbol

## IRFP241
designator Q?
N-Channel MOSFET
simulation model IRFP241 (SUBCKT)
pins: 1 D (in), 2 G (in), 3 S (in)
1 alternate drawing of the same symbol

## IRFP242
designator Q?
N-Channel MOSFET
simulation model IRFP242 (SUBCKT)
pins: 1 D (in), 2 G (in), 3 S (in)
1 alternate drawing of the same symbol

## IRFP243
designator Q?
N-Channel MOSFET
simulation model IRFP243 (SUBCKT)
pins: 1 D (in), 2 G (in), 3 S (in)
1 alternate drawing of the same symbol

## IRFP244
designator Q?
N-Channel MOSFET
simulation model IRFP244 (SUBCKT)
pins: 1 D (in), 2 G (in), 3 S (in)
1 alternate drawing of the same symbol

## IRFP250
designator Q?
N-Channel MOSFET
simulation model IRFP250 (SUBCKT)
pins: 1 D (in), 2 G (in), 3 S (in)
1 alternate drawing of the same symbol

## IRFP251
designator Q?
N-Channel MOSFET
simulation model IRFP251 (SUBCKT)
pins: 1 D (in), 2 G (in), 3 S (in)
1 alternate drawing of the same symbol

## IRFP252
designator Q?
N-Channel MOSFET
simulation model IRFP252 (SUBCKT)
pins: 1 D (in), 2 G (in), 3 S (in)
1 alternate drawing of the same symbol

## IRFP253
designator Q?
N-Channel MOSFET
simulation model IRFP253 (SUBCKT)
pins: 1 D (in), 2 G (in), 3 S (in)
1 alternate drawing of the same symbol

## IRFP254
designator Q?
N-Channel MOSFET
simulation model IRFP254 (SUBCKT)
pins: 1 D (in), 2 G (in), 3 S (in)
1 alternate drawing of the same symbol

## IRFP260
designator Q?
N-Channel MOSFET
simulation model IRFP260 (SUBCKT)
pins: 1 D (in), 2 G (in), 3 S (in)
1 alternate drawing of the same symbol

## IRFP264
designator Q?
N-Channel MOSFET
simulation model IRFP264 (SUBCKT)
pins: 1 D (in), 2 G (in), 3 S (in)
1 alternate drawing of the same symbol

## IRFP340
designator Q?
N-Channel MOSFET
simulation model IRFP340 (SUBCKT)
pins: 1 D (in), 2 G (in), 3 S (in)
1 alternate drawing of the same symbol

## IRFP344
designator Q?
N-Channel MOSFET
simulation model IRFP344 (SUBCKT)
pins: 1 D (in), 2 G (in), 3 S (in)
1 alternate drawing of the same symbol

## IRFP350
designator Q?
N-Channel MOSFET
simulation model IRFP350 (SUBCKT)
pins: 1 D (in), 2 G (in), 3 S (in)
1 alternate drawing of the same symbol

## IRFP350LC
designator Q?
N-Channel MOSFET
simulation model IRFP350LC (SUBCKT)
pins: 1 D (in), 2 G (in), 3 S (in)
1 alternate drawing of the same symbol

## IRFP351
designator Q?
N-Channel MOSFET
simulation model IRFP351 (SUBCKT)
pins: 1 D (in), 2 G (in), 3 S (in)
1 alternate drawing of the same symbol

## IRFP352
designator Q?
N-Channel MOSFET
simulation model IRFP352 (SUBCKT)
pins: 1 D (in), 2 G (in), 3 S (in)
1 alternate drawing of the same symbol

## IRFP353
designator Q?
N-Channel MOSFET
simulation model IRFP353 (SUBCKT)
pins: 1 D (in), 2 G (in), 3 S (in)
1 alternate drawing of the same symbol

## IRFP354
designator Q?
N-Channel MOSFET
simulation model IRFP354 (SUBCKT)
pins: 1 D (in), 2 G (in), 3 S (in)
1 alternate drawing of the same symbol

## IRFP360
designator Q?
N-Channel MOSFET
simulation model IRFP360 (SUBCKT)
pins: 1 D (in), 2 G (in), 3 S (in)
1 alternate drawing of the same symbol

## IRFP360LC
designator Q?
N-Channel MOSFET
simulation model IRFP360LC (SUBCKT)
pins: 1 D (in), 2 G (in), 3 S (in)
1 alternate drawing of the same symbol

## IRFP362
designator Q?
N-Channel MOSFET
simulation model IRFP362 (SUBCKT)
pins: 1 D (in), 2 G (in), 3 S (in)
1 alternate drawing of the same symbol

## IRFP440
designator Q?
N-Channel MOSFET
simulation model IRFP440 (SUBCKT)
pins: 1 D (in), 2 G (in), 3 S (in)
1 alternate drawing of the same symbol

## IRFP448
designator Q?
N-Channel MOSFET
simulation model IRFP448 (SUBCKT)
pins: 1 D (in), 2 G (in), 3 S (in)
1 alternate drawing of the same symbol

## IRFP450
designator Q?
N-Channel MOSFET
simulation model IRFP450 (SUBCKT)
pins: 1 D (in), 2 G (in), 3 S (in)
1 alternate drawing of the same symbol

## IRFP450LC
designator Q?
N-Channel MOSFET
simulation model IRFP450LC (SUBCKT)
pins: 1 D (in), 2 G (in), 3 S (in)
1 alternate drawing of the same symbol

## IRFP451
designator Q?
N-Channel MOSFET
simulation model IRFP451 (SUBCKT)
pins: 1 D (in), 2 G (in), 3 S (in)
1 alternate drawing of the same symbol

## IRFP452
designator Q?
N-Channel MOSFET
simulation model IRFP452 (SUBCKT)
pins: 1 D (in), 2 G (in), 3 S (in)
1 alternate drawing of the same symbol

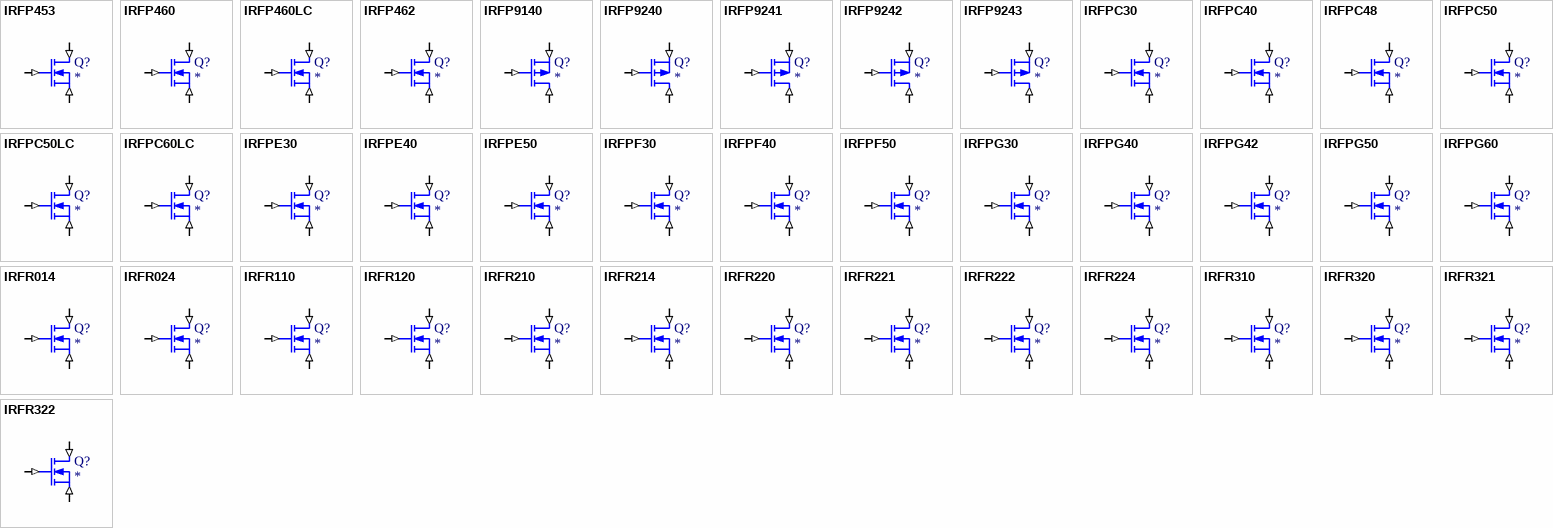
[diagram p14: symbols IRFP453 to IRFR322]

## IRFP453
designator Q?
N-Channel MOSFET
simulation model IRFP453 (SUBCKT)
pins: 1 D (in), 2 G (in), 3 S (in)
1 alternate drawing of the same symbol

## IRFP460
designator Q?
N-Channel MOSFET
simulation model IRFP460 (SUBCKT)
pins: 1 D (in), 2 G (in), 3 S (in)
1 alternate drawing of the same symbol

## IRFP460LC
designator Q?
N-Channel MOSFET
simulation model IRFP460LC (SUBCKT)
pins: 1 D (in), 2 G (in), 3 S (in)
1 alternate drawing of the same symbol

## IRFP462
designator Q?
N-Channel MOSFET
simulation model IRFP462 (SUBCKT)
pins: 1 D (in), 2 G (in), 3 S (in)
1 alternate drawing of the same symbol

## IRFP9140
designator Q?
P-Channel MOSFET
simulation model IRFP9140 (SUBCKT)
pins: 1 D (in), 2 G (in), 3 S (in)
1 alternate drawing of the same symbol

## IRFP9240
designator Q?
P-Channel MOSFET
simulation model IRFP9240 (SUBCKT)
pins: 1 D (in), 2 G (in), 3 S (in)
1 alternate drawing of the same symbol

## IRFP9241
designator Q?
P-Channel MOSFET
simulation model IRFP9241 (SUBCKT)
pins: 1 D (in), 2 G (in), 3 S (in)
1 alternate drawing of the same symbol

## IRFP9242
designator Q?
P-Channel MOSFET
simulation model IRFP9242 (SUBCKT)
pins: 1 D (in), 2 G (in), 3 S (in)
1 alternate drawing of the same symbol

## IRFP9243
designator Q?
P-Channel MOSFET
simulation model IRFP9243 (SUBCKT)
pins: 1 D (in), 2 G (in), 3 S (in)
1 alternate drawing of the same symbol

## IRFPC30
designator Q?
N-Channel MOSFET
simulation model IRFPC30 (SUBCKT)
pins: 1 D (in), 2 G (in), 3 S (in)
1 alternate drawing of the same symbol

## IRFPC40
designator Q?
N-Channel MOSFET
simulation model IRFPC40 (SUBCKT)
pins: 1 D (in), 2 G (in), 3 S (in)
1 alternate drawing of the same symbol

## IRFPC48
designator Q?
N-Channel MOSFET
simulation model IRFPC48 (SUBCKT)
pins: 1 D (in), 2 G (in), 3 S (in)
1 alternate drawing of the same symbol

## IRFPC50
designator Q?
N-Channel MOSFET
simulation model IRFPC50 (SUBCKT)
pins: 1 D (in), 2 G (in), 3 S (in)
1 alternate drawing of the same symbol

## IRFPC50LC
designator Q?
N-Channel MOSFET
simulation model IRFPC50LC (SUBCKT)
pins: 1 D (in), 2 G (in), 3 S (in)
1 alternate drawing of the same symbol

## IRFPC60LC
designator Q?
N-Channel MOSFET
simulation model IRFPC60LC (SUBCKT)
pins: 1 D (in), 2 G (in), 3 S (in)
1 alternate drawing of the same symbol

## IRFPE30
designator Q?
N-Channel MOSFET
simulation model IRFPE30 (SUBCKT)
pins: 1 D (in), 2 G (in), 3 S (in)
1 alternate drawing of the same symbol

## IRFPE40
designator Q?
N-Channel MOSFET
simulation model IRFPE40 (SUBCKT)
pins: 1 D (in), 2 G (in), 3 S (in)
1 alternate drawing of the same symbol

## IRFPE50
designator Q?
N-Channel MOSFET
simulation model IRFPE50 (SUBCKT)
pins: 1 D (in), 2 G (in), 3 S (in)
1 alternate drawing of the same symbol

## IRFPF30
designator Q?
N-Channel MOSFET
simulation model IRFPF30 (SUBCKT)
pins: 1 D (in), 2 G (in), 3 S (in)
1 alternate drawing of the same symbol

## IRFPF40
designator Q?
N-Channel MOSFET
simulation model IRFPF40 (SUBCKT)
pins: 1 D (in), 2 G (in), 3 S (in)
1 alternate drawing of the same symbol

## IRFPF50
designator Q?
N-Channel MOSFET
simulation model IRFPF50 (SUBCKT)
pins: 1 D (in), 2 G (in), 3 S (in)
1 alternate drawing of the same symbol

## IRFPG30
designator Q?
N-Channel MOSFET
simulation model IRFPG30 (SUBCKT)
pins: 1 D (in), 2 G (in), 3 S (in)
1 alternate drawing of the same symbol

## IRFPG40
designator Q?
N-Channel MOSFET
simulation model IRFPG40 (SUBCKT)
pins: 1 D (in), 2 G (in), 3 S (in)
1 alternate drawing of the same symbol

## IRFPG42
designator Q?
N-Channel MOSFET
simulation model IRFPG42 (SUBCKT)
pins: 1 D (in), 2 G (in), 3 S (in)
1 alternate drawing of the same symbol

## IRFPG50
designator Q?
N-Channel MOSFET
simulation model IRFPG50 (SUBCKT)
pins: 1 D (in), 2 G (in), 3 S (in)
1 alternate drawing of the same symbol

## IRFPG60
designator Q?
N-Channel MOSFET
simulation model IRFPG60 (SUBCKT)
pins: 1 D (in), 2 G (in), 3 S (in)
1 alternate drawing of the same symbol

## IRFR014
designator Q?
N-Channel MOSFET
simulation model IRFR014 (SUBCKT)
pins: 1 D (in), 2 G (in), 3 S (in)
1 alternate drawing of the same symbol

## IRFR024
designator Q?
N-Channel MOSFET
simulation model IRFR024 (SUBCKT)
pins: 1 D (in), 2 G (in), 3 S (in)
1 alternate drawing of the same symbol

## IRFR110
designator Q?
N-Channel MOSFET
simulation model IRFR110 (SUBCKT)
pins: 1 D (in), 2 G (in), 3 S (in)
1 alternate drawing of the same symbol

## IRFR120
designator Q?
N-Channel MOSFET
simulation model IRFR120 (SUBCKT)
pins: 1 D (in), 2 G (in), 3 S (in)
1 alternate drawing of the same symbol

## IRFR210
designator Q?
N-Channel MOSFET
simulation model IRFR210 (SUBCKT)
pins: 1 D (in), 2 G (in), 3 S (in)
1 alternate drawing of the same symbol

## IRFR214
designator Q?
N-Channel MOSFET
simulation model IRFR214 (SUBCKT)
pins: 1 D (in), 2 G (in), 3 S (in)
1 alternate drawing of the same symbol

## IRFR220
designator Q?
N-Channel MOSFET
simulation model IRFR220 (SUBCKT)
pins: 1 D (in), 2 G (in), 3 S (in)
1 alternate drawing of the same symbol

## IRFR221
designator Q?
N-Channel MOSFET
simulation model IRFR221 (SUBCKT)
pins: 1 D (in), 2 G (in), 3 S (in)
1 alternate drawing of the same symbol

## IRFR222
designator Q?
N-Channel MOSFET
simulation model IRFR222 (SUBCKT)
pins: 1 D (in), 2 G (in), 3 S (in)
1 alternate drawing of the same symbol

## IRFR224
designator Q?
N-Channel MOSFET
simulation model IRFR224 (SUBCKT)
pins: 1 D (in), 2 G (in), 3 S (in)
1 alternate drawing of the same symbol

## IRFR310
designator Q?
N-Channel MOSFET
simulation model IRFR310 (SUBCKT)
pins: 1 D (in), 2 G (in), 3 S (in)
1 alternate drawing of the same symbol

## IRFR320
designator Q?
N-Channel MOSFET
simulation model IRFR320 (SUBCKT)
pins: 1 D (in), 2 G (in), 3 S (in)
1 alternate drawing of the same symbol

## IRFR321
designator Q?
N-Channel MOSFET
simulation model IRFR321 (SUBCKT)
pins: 1 D (in), 2 G (in), 3 S (in)
1 alternate drawing of the same symbol

## IRFR322
designator Q?
N-Channel MOSFET
simulation model IRFR322 (SUBCKT)
pins: 1 D (in), 2 G (in), 3 S (in)
1 alternate drawing of the same symbol

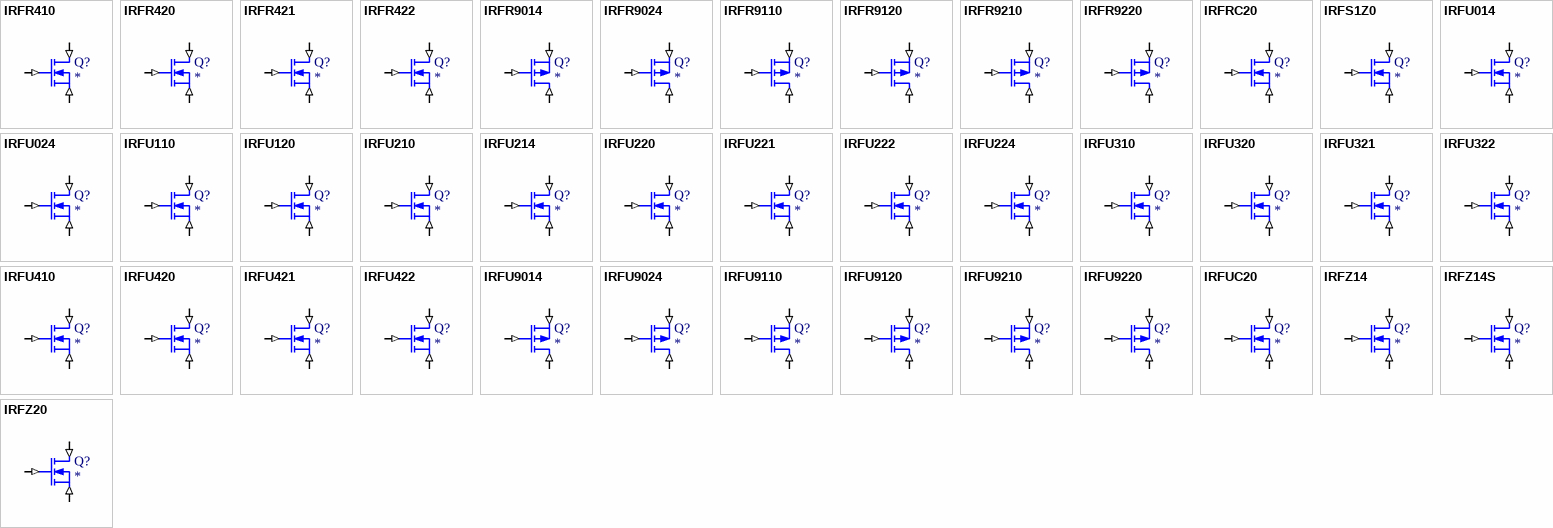
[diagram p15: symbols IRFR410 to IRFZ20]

## IRFR410
designator Q?
N-Channel MOSFET
simulation model IRFR410 (SUBCKT)
pins: 1 D (in), 2 G (in), 3 S (in)
1 alternate drawing of the same symbol

## IRFR420
designator Q?
N-Channel MOSFET
simulation model IRFR420 (SUBCKT)
pins: 1 D (in), 2 G (in), 3 S (in)
1 alternate drawing of the same symbol

## IRFR421
designator Q?
N-Channel MOSFET
simulation model IRFR421 (SUBCKT)
pins: 1 D (in), 2 G (in), 3 S (in)
1 alternate drawing of the same symbol

## IRFR422
designator Q?
N-Channel MOSFET
simulation model IRFR422 (SUBCKT)
pins: 1 D (in), 2 G (in), 3 S (in)
1 alternate drawing of the same symbol

## IRFR9014
designator Q?
P-Channel MOSFET
simulation model IRFR9014 (SUBCKT)
pins: 1 D (in), 2 G (in), 3 S (in)
1 alternate drawing of the same symbol

## IRFR9024
designator Q?
P-Channel MOSFET
simulation model IRFR9024 (SUBCKT)
pins: 1 D (in), 2 G (in), 3 S (in)
1 alternate drawing of the same symbol

## IRFR9110
designator Q?
P-Channel MOSFET
simulation model IRFR9110 (SUBCKT)
pins: 1 D (in), 2 G (in), 3 S (in)
1 alternate drawing of the same symbol

## IRFR9120
designator Q?
P-Channel MOSFET
simulation model IRFR9120 (SUBCKT)
pins: 1 D (in), 2 G (in), 3 S (in)
1 alternate drawing of the same symbol

## IRFR9210
designator Q?
P-Channel MOSFET
simulation model IRFR9210 (SUBCKT)
pins: 1 D (in), 2 G (in), 3 S (in)
1 alternate drawing of the same symbol

## IRFR9220
designator Q?
P-Channel MOSFET
simulation model IRFR9220 (SUBCKT)
pins: 1 D (in), 2 G (in), 3 S (in)
1 alternate drawing of the same symbol

## IRFRC20
designator Q?
N-Channel MOSFET
simulation model IRFRC20 (SUBCKT)
pins: 1 D (in), 2 G (in), 3 S (in)
1 alternate drawing of the same symbol

## IRFS1Z0
designator Q?
N-Channel MOSFET
simulation model IRFS1Z0 (SUBCKT)
pins: 1 D (in), 2 G (in), 3 S (in)
1 alternate drawing of the same symbol

## IRFU014
designator Q?
N-Channel MOSFET
simulation model IRFU014 (SUBCKT)
pins: 1 D (in), 2 G (in), 3 S (in)
1 alternate drawing of the same symbol

## IRFU024
designator Q?
N-Channel MOSFET
simulation model IRFU024 (SUBCKT)
pins: 1 D (in), 2 G (in), 3 S (in)
1 alternate drawing of the same symbol

## IRFU110
designator Q?
N-Channel MOSFET
simulation model IRFU110 (SUBCKT)
pins: 1 D (in), 2 G (in), 3 S (in)
1 alternate drawing of the same symbol

## IRFU120
designator Q?
N-Channel MOSFET
simulation model IRFU120 (SUBCKT)
pins: 1 D (in), 2 G (in), 3 S (in)
1 alternate drawing of the same symbol

## IRFU210
designator Q?
N-Channel MOSFET
simulation model IRFU210 (SUBCKT)
pins: 1 D (in), 2 G (in), 3 S (in)
1 alternate drawing of the same symbol

## IRFU214
designator Q?
N-Channel MOSFET
simulation model IRFU214 (SUBCKT)
pins: 1 D (in), 2 G (in), 3 S (in)
1 alternate drawing of the same symbol

## IRFU220
designator Q?
N-Channel MOSFET
simulation model IRFU220 (SUBCKT)
pins: 1 D (in), 2 G (in), 3 S (in)
1 alternate drawing of the same symbol

## IRFU221
designator Q?
N-Channel MOSFET
simulation model IRFU221 (SUBCKT)
pins: 1 D (in), 2 G (in), 3 S (in)
1 alternate drawing of the same symbol

## IRFU222
designator Q?
N-Channel MOSFET
simulation model IRFU222 (SUBCKT)
pins: 1 D (in), 2 G (in), 3 S (in)
1 alternate drawing of the same symbol

## IRFU224
designator Q?
N-Channel MOSFET
simulation model IRFU224 (SUBCKT)
pins: 1 D (in), 2 G (in), 3 S (in)
1 alternate drawing of the same symbol

## IRFU310
designator Q?
N-Channel MOSFET
simulation model IRFU310 (SUBCKT)
pins: 1 D (in), 2 G (in), 3 S (in)
1 alternate drawing of the same symbol

## IRFU320
designator Q?
N-Channel MOSFET
simulation model IRFU320 (SUBCKT)
pins: 1 D (in), 2 G (in), 3 S (in)
1 alternate drawing of the same symbol

## IRFU321
designator Q?
N-Channel MOSFET
simulation model IRFU321 (SUBCKT)
pins: 1 D (in), 2 G (in), 3 S (in)
1 alternate drawing of the same symbol

## IRFU322
designator Q?
N-Channel MOSFET
simulation model IRFU322 (SUBCKT)
pins: 1 D (in), 2 G (in), 3 S (in)
1 alternate drawing of the same symbol

## IRFU410
designator Q?
N-Channel MOSFET
simulation model IRFU410 (SUBCKT)
pins: 1 D (in), 2 G (in), 3 S (in)
1 alternate drawing of the same symbol

## IRFU420
designator Q?
N-Channel MOSFET
simulation model IRFU420 (SUBCKT)
pins: 1 D (in), 2 G (in), 3 S (in)
1 alternate drawing of the same symbol

## IRFU421
designator Q?
N-Channel MOSFET
simulation model IRFU421 (SUBCKT)
pins: 1 D (in), 2 G (in), 3 S (in)
1 alternate drawing of the same symbol

## IRFU422
designator Q?
N-Channel MOSFET
simulation model IRFU422 (SUBCKT)
pins: 1 D (in), 2 G (in), 3 S (in)
1 alternate drawing of the same symbol

## IRFU9014
designator Q?
P-Channel MOSFET
simulation model IRFU9014 (SUBCKT)
pins: 1 D (in), 2 G (in), 3 S (in)
1 alternate drawing of the same symbol

## IRFU9024
designator Q?
P-Channel MOSFET
simulation model IRFU9024 (SUBCKT)
pins: 1 D (in), 2 G (in), 3 S (in)
1 alternate drawing of the same symbol

## IRFU9110
designator Q?
P-Channel MOSFET
simulation model IRFU9110 (SUBCKT)
pins: 1 D (in), 2 G (in), 3 S (in)
1 alternate drawing of the same symbol

## IRFU9120
designator Q?
P-Channel MOSFET
simulation model IRFU9120 (SUBCKT)
pins: 1 D (in), 2 G (in), 3 S (in)
1 alternate drawing of the same symbol

## IRFU9210
designator Q?
P-Channel MOSFET
simulation model IRFU9210 (SUBCKT)
pins: 1 D (in), 2 G (in), 3 S (in)
1 alternate drawing of the same symbol

## IRFU9220
designator Q?
P-Channel MOSFET
simulation model IRFU9220 (SUBCKT)
pins: 1 D (in), 2 G (in), 3 S (in)
1 alternate drawing of the same symbol

## IRFUC20
designator Q?
N-Channel MOSFET
simulation model IRFUC20 (SUBCKT)
pins: 1 D (in), 2 G (in), 3 S (in)
1 alternate drawing of the same symbol

## IRFZ14
designator Q?
N-Channel MOSFET
simulation model IRFZ14 (SUBCKT)
pins: 1 D (in), 2 G (in), 3 S (in)
1 alternate drawing of the same symbol

## IRFZ14S
designator Q?
N-Channel MOSFET
simulation model IRFZ14S (SUBCKT)
pins: 1 D (in), 2 G (in), 3 S (in)
1 alternate drawing of the same symbol

## IRFZ20
designator Q?
N-Channel MOSFET
simulation model IRFZ20 (SUBCKT)
pins: 1 D (in), 2 G (in), 3 S (in)
1 alternate drawing of the same symbol

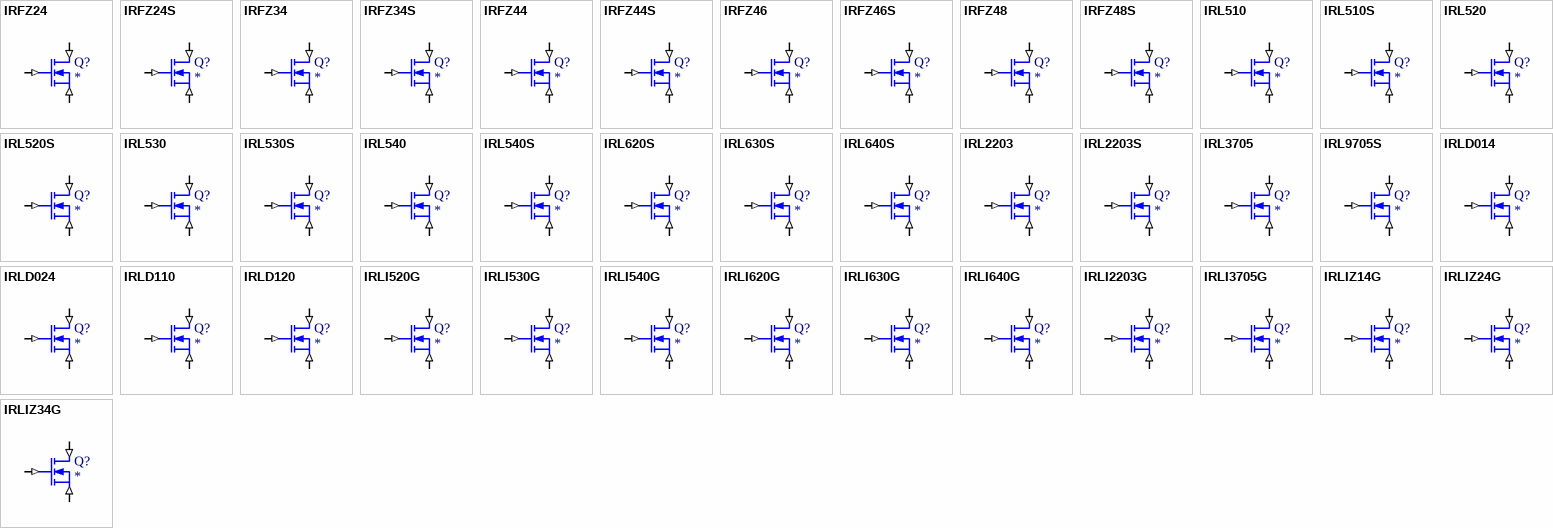
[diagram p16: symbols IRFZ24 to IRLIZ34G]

## IRFZ24
designator Q?
N-Channel MOSFET
simulation model IRFZ24 (SUBCKT)
pins: 1 D (in), 2 G (in), 3 S (in)
1 alternate drawing of the same symbol

## IRFZ24S
designator Q?
N-Channel MOSFET
simulation model IRFZ24S (SUBCKT)
pins: 1 D (in), 2 G (in), 3 S (in)
1 alternate drawing of the same symbol

## IRFZ34
designator Q?
N-Channel MOSFET
simulation model IRFZ34 (SUBCKT)
pins: 1 D (in), 2 G (in), 3 S (in)
1 alternate drawing of the same symbol

## IRFZ34S
designator Q?
N-Channel MOSFET
simulation model IRFZ34S (SUBCKT)
pins: 1 D (in), 2 G (in), 3 S (in)
1 alternate drawing of the same symbol

## IRFZ44
designator Q?
N-Channel MOSFET
simulation model IRFZ44 (SUBCKT)
pins: 1 D (in), 2 G (in), 3 S (in)
1 alternate drawing of the same symbol

## IRFZ44S
designator Q?
N-Channel MOSFET
simulation model IRFZ44S (SUBCKT)
pins: 1 D (in), 2 G (in), 3 S (in)
1 alternate drawing of the same symbol

## IRFZ46
designator Q?
N-Channel MOSFET
simulation model IRFZ46 (SUBCKT)
pins: 1 D (in), 2 G (in), 3 S (in)
1 alternate drawing of the same symbol

## IRFZ46S
designator Q?
N-Channel MOSFET
simulation model IRFZ46S (SUBCKT)
pins: 1 D (in), 2 G (in), 3 S (in)
1 alternate drawing of the same symbol

## IRFZ48
designator Q?
N-Channel MOSFET
simulation model IRFZ48 (SUBCKT)
pins: 1 D (in), 2 G (in), 3 S (in)
1 alternate drawing of the same symbol

## IRFZ48S
designator Q?
N-Channel MOSFET
simulation model IRFZ48S (SUBCKT)
pins: 1 D (in), 2 G (in), 3 S (in)
1 alternate drawing of the same symbol

## IRL510
designator Q?
N-Channel MOSFET
simulation model IRL510 (SUBCKT)
pins: 1 D (in), 2 G (in), 3 S (in)
1 alternate drawing of the same symbol

## IRL510S
designator Q?
N-Channel MOSFET
simulation model IRL510S (SUBCKT)
pins: 1 D (in), 2 G (in), 3 S (in)
1 alternate drawing of the same symbol

## IRL520
designator Q?
N-Channel MOSFET
simulation model IRL520 (SUBCKT)
pins: 1 D (in), 2 G (in), 3 S (in)
1 alternate drawing of the same symbol

## IRL520S
designator Q?
N-Channel MOSFET
simulation model IRL520S (SUBCKT)
pins: 1 D (in), 2 G (in), 3 S (in)
1 alternate drawing of the same symbol

## IRL530
designator Q?
N-Channel MOSFET
simulation model IRL530 (SUBCKT)
pins: 1 D (in), 2 G (in), 3 S (in)
1 alternate drawing of the same symbol

## IRL530S
designator Q?
N-Channel MOSFET
simulation model IRL530S (SUBCKT)
pins: 1 D (in), 2 G (in), 3 S (in)
1 alternate drawing of the same symbol

## IRL540
designator Q?
N-Channel MOSFET
simulation model IRL540 (SUBCKT)
pins: 1 D (in), 2 G (in), 3 S (in)
1 alternate drawing of the same symbol

## IRL540S
designator Q?
N-Channel MOSFET
simulation model IRL540S (SUBCKT)
pins: 1 D (in), 2 G (in), 3 S (in)
1 alternate drawing of the same symbol

## IRL620S
designator Q?
N-Channel MOSFET
simulation model IRL620S (SUBCKT)
pins: 1 D (in), 2 G (in), 3 S (in)
1 alternate drawing of the same symbol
